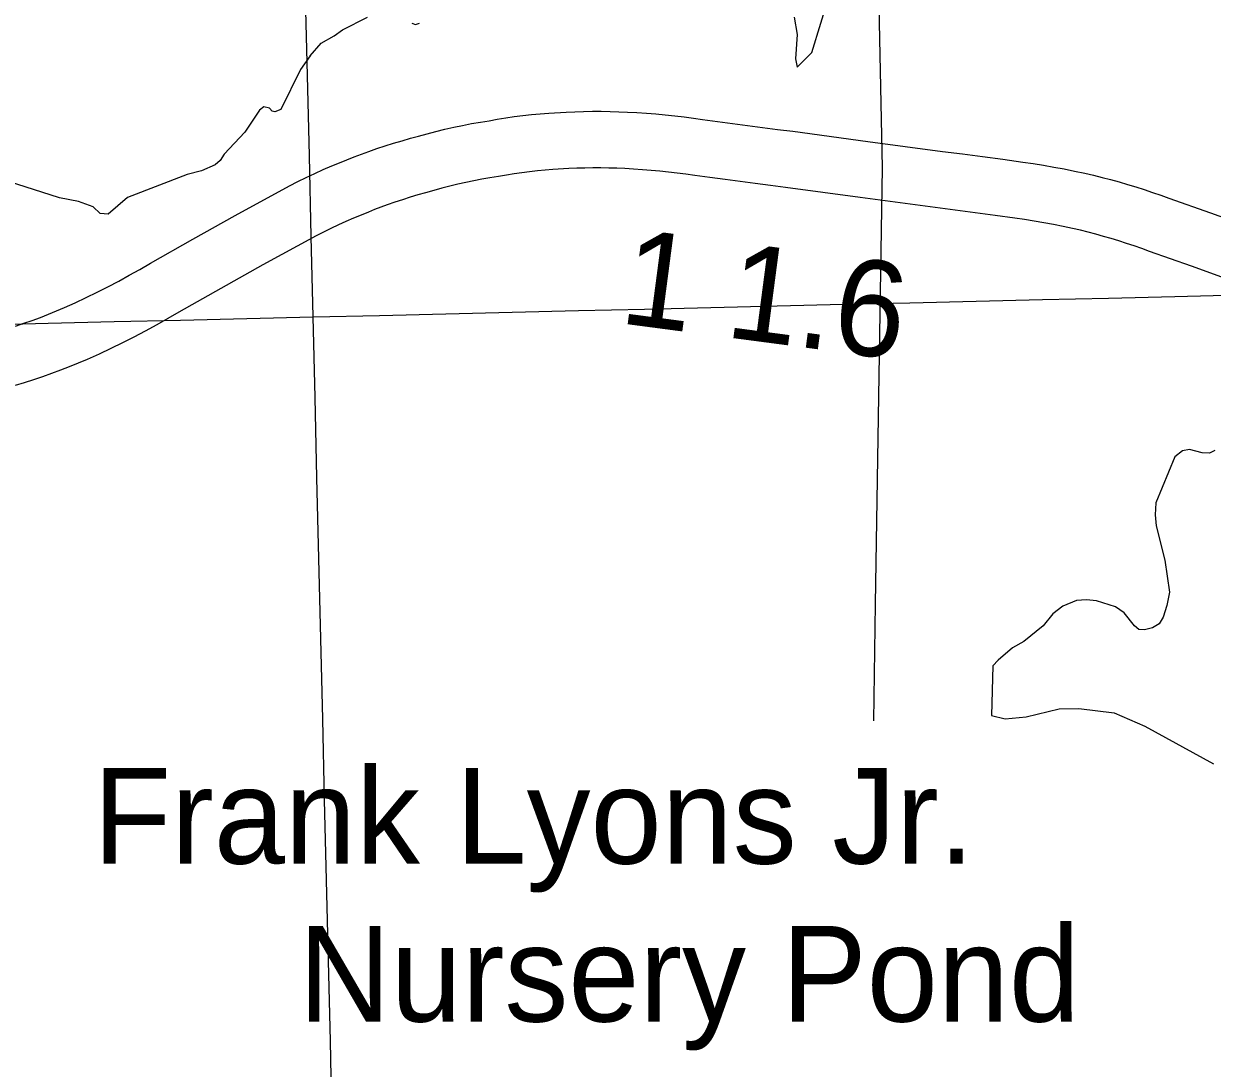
# Model space of a CAD drawing. Extents: x -19 to 366, y -4 to 359.
# Drawn here: x 134.672 to 135.666, y 199.103 to 199.977 of the extents above; entities that cross this region are included whole.
import ezdxf

# ---------------------------------------------------------------- set-up
doc = ezdxf.new("R2010")
doc.units = 0
for name, color, linetype in [('R_Axis Annot', 7, 'Continuous'), ('R_Border Prem', 7, 'Continuous'), ('R_Contour Annot', 7, 'Continuous'), ('R_Temp Easement', 7, 'Continuous'), ('Sheet Fence', 7, 'Continuous'), ('T_Vehicle Path Lt Minor', 7, 'Continuous')]:
    doc.layers.add(name, color=color, linetype=linetype)

msp = doc.modelspace()

# ---------------------------------------------------------------- linework, layer by layer
at = {"layer": 'R_Axis Annot'}
msp.add_lwpolyline([(135.38312, 199.3934), (135.3847, 199.49111), (135.39059, 199.85615), (135.38554, 200.09948)], dxfattribs=at)
at = {"layer": 'R_Border Prem'}
for points in [[(135.31655, 199.98229), (135.31921, 199.96788), (135.31771, 199.94739), (135.31923, 199.94056), (135.33132, 199.95271), (135.34639, 200.00202)], [(134.91173, 199.94991), (134.92079, 199.96054), (134.93175, 199.96661), (134.93855, 199.97154), (134.95971, 199.98217)], [(134.99676, 199.97725), (134.99978, 199.97611), (135.00318, 199.97725)], [(134.91173, 199.94991), (134.90357, 199.93839), (134.88704, 199.90515), (134.88215, 199.90319), (134.87987, 199.90353), (134.87756, 199.90616), (134.873, 199.90723), (134.86926, 199.90452), (134.85705, 199.88614), (134.83954, 199.86769), (134.83621, 199.86233), (134.8321, 199.85886), (134.82082, 199.85377), (134.80876, 199.85056), (134.75871, 199.83127), (134.74264, 199.81738), (134.73582, 199.81805), (134.73006, 199.82366), (134.71788, 199.82804), (134.70193, 199.83123), (134.63118, 199.85376)]]:
    msp.add_lwpolyline(points, dxfattribs=at)
at = {"layer": 'R_Contour Annot'}
for points in [[(134.96065, 199.86996), (134.96745, 199.87231), (134.97444, 199.87461), (134.98146, 199.87682), (134.98851, 199.87894), (134.99557, 199.88095), (135.00239, 199.8828), (135.00947, 199.88478), (135.01685, 199.88671), (135.02427, 199.88852), (135.03171, 199.89021), (135.03918, 199.89177), (135.04668, 199.89321), (135.0542, 199.89452), (135.0613, 199.89564), (135.06803, 199.89685), (135.07521, 199.89801), (135.08245, 199.89905), (135.08965, 199.89997), (135.0969, 199.90077), (135.10416, 199.90145), (135.11141, 199.90201), (135.1257, 199.90287), (135.13306, 199.9032), (135.14045, 199.90341), (135.14781, 199.90351), (135.15521, 199.90351), (135.16258, 199.90339), (135.16996, 199.90315), (135.17722, 199.90281), (135.18506, 199.9024), (135.19296, 199.90189), (135.20087, 199.90127), (135.20875, 199.90054), (135.21663, 199.89972), (135.22452, 199.89879), (135.23237, 199.89776), (135.23995, 199.89666), (135.25243, 199.89498), (135.265, 199.8933), (135.27756, 199.89164), (135.29015, 199.89), (135.30273, 199.88838), (135.31546, 199.88677), (135.37812, 199.87828), (135.4407, 199.87), (135.45745, 199.86784), (135.47428, 199.86563), (135.4911, 199.86337), (135.508, 199.86104), (135.51667, 199.85975), (135.52532, 199.85836), (135.53395, 199.85686), (135.54259, 199.85526), (135.55119, 199.85356), (135.55989, 199.85173), (135.56714, 199.85003), (135.57427, 199.84826), (135.58136, 199.8464), (135.58844, 199.84445), (135.59548, 199.8424), (135.60251, 199.84026), (135.60947, 199.83802), (135.61641, 199.8357), (135.62333, 199.83329), (135.62997, 199.83088), (135.66484, 199.8186), (135.69979, 199.80602)], [(134.66519, 199.72377), (134.67212, 199.72612), (134.67901, 199.72857), (134.68587, 199.73111), (134.69269, 199.73375), (134.69947, 199.7365), (134.70607, 199.73927), (134.71513, 199.74339), (134.72429, 199.74771), (134.73339, 199.75216), (134.74243, 199.75675), (134.75142, 199.76146), (134.76031, 199.76629), (134.76913, 199.77125), (134.77817, 199.7765), (134.81352, 199.79647), (134.84897, 199.81639), (134.89437, 199.84114), (134.90135, 199.84475), (134.90834, 199.84821), (134.91544, 199.85156), (134.92259, 199.85477), (134.92976, 199.85783), (134.93757, 199.861), (134.94229, 199.86301), (134.94839, 199.86545), (134.9545, 199.86777), (134.96065, 199.86996)], [(135.68364, 199.76151), (135.64896, 199.774), (135.61403, 199.78629), (135.60745, 199.78868), (135.60111, 199.7909), (135.59474, 199.79302), (135.58837, 199.79507), (135.58196, 199.79702), (135.57552, 199.79889), (135.56904, 199.80068), (135.56256, 199.80239), (135.55605, 199.804), (135.54961, 199.80551), (135.54172, 199.80717), (135.53369, 199.80876), (135.5256, 199.81025), (135.51752, 199.81166), (135.50942, 199.81296), (135.50129, 199.81417), (135.48471, 199.81645), (135.46804, 199.8187), (135.45134, 199.82089), (135.43457, 199.82305), (135.37183, 199.83135), (135.30931, 199.83982), (135.29674, 199.84142), (135.28407, 199.84304), (135.27141, 199.8447), (135.25877, 199.84636), (135.24613, 199.84805), (135.2334, 199.84977), (135.2259, 199.85085), (135.21867, 199.8518), (135.2114, 199.85266), (135.20412, 199.85342), (135.19685, 199.85409), (135.18956, 199.85466), (135.18228, 199.85514), (135.17488, 199.85552), (135.16811, 199.85584), (135.16145, 199.85605), (135.15479, 199.85616), (135.14812, 199.85617), (135.14147, 199.85607), (135.1348, 199.85588), (135.12816, 199.85558), (135.11465, 199.85477), (135.10819, 199.85427), (135.1017, 199.85367), (135.09526, 199.85296), (135.08883, 199.85213), (135.08238, 199.85121), (135.07599, 199.85017), (135.06915, 199.84895), (135.06197, 199.84781), (135.05521, 199.84663), (135.04848, 199.84535), (135.04179, 199.84394), (135.03511, 199.84243), (135.02847, 199.84081), (135.02184, 199.83908), (135.01497, 199.83716), (135.00826, 199.83533), (135.0018, 199.83349), (134.99537, 199.83156), (134.98897, 199.82955), (134.9826, 199.82745), (134.97612, 199.82521)], [(134.97612, 199.82521), (134.97084, 199.82332), (134.96557, 199.82133), (134.96035, 199.81924), (134.95575, 199.81728), (134.94798, 199.81413), (134.94158, 199.81139), (134.93523, 199.80854), (134.92897, 199.80559), (134.92275, 199.8025), (134.91658, 199.79931), (134.87189, 199.77496), (134.83676, 199.75522), (134.8017, 199.73541), (134.79262, 199.73014), (134.78322, 199.72486), (134.77371, 199.71969), (134.76414, 199.71467), (134.75451, 199.70978), (134.7448, 199.70503), (134.73504, 199.70043), (134.72504, 199.69588), (134.71751, 199.69272), (134.71011, 199.68973), (134.70265, 199.68684), (134.69518, 199.68406), (134.68763, 199.68139), (134.68007, 199.67882), (134.67247, 199.67636), (134.66484, 199.67401)]]:
    msp.add_lwpolyline(points, dxfattribs=at)
at = {"layer": 'R_Temp Easement'}
msp.add_lwpolyline([(135.66857, 199.61979), (135.66407, 199.61744), (135.65802, 199.61772), (135.64739, 199.62057), (135.64137, 199.61933), (135.63503, 199.61429), (135.61908, 199.57607), (135.6185, 199.56581), (135.61942, 199.55672), (135.62672, 199.52801), (135.63059, 199.50113), (135.62852, 199.49009), (135.62529, 199.48017), (135.62199, 199.4748), (135.61638, 199.47129), (135.60961, 199.46966), (135.60507, 199.46996), (135.60124, 199.47293), (135.59273, 199.48379), (135.58546, 199.48898), (135.5695, 199.49402), (135.56118, 199.49464), (135.55288, 199.49412), (135.54125, 199.48936), (135.53304, 199.48315), (135.5249, 199.47315), (135.50889, 199.45997), (135.49916, 199.45449), (135.48724, 199.44443), (135.4828, 199.43942), (135.48163, 199.39803), (135.49302, 199.39519), (135.51075, 199.39701), (135.53821, 199.40355), (135.55484, 199.40383), (135.58437, 199.40016), (135.60988, 199.38921), (135.66749, 199.35756)], dxfattribs=at)
at = {"layer": 'Sheet Fence'}
for points in [[(139.44064, 1.53154), (139.25106, 10.14733), (139.06082, 18.76327), (138.86992, 27.37935), (138.67836, 35.99557), (138.48613, 44.61194), (138.29325, 53.22845), (138.09971, 61.84511), (137.9055, 70.46191), (137.71065, 79.07885), (137.51513, 87.69595), (137.31896, 96.31318), (137.12214, 104.93057), (136.92466, 113.54809), (136.72653, 122.16577), (136.52775, 130.78359), (136.32832, 139.40156), (136.12824, 148.01968), (135.9275, 156.63794), (135.72612, 165.25636), (135.5241, 173.87492), (135.32143, 182.49362), (135.11811, 191.11248), (134.91415, 199.73149), (134.70954, 208.35064), (134.50429, 216.96995), (134.2984, 225.5894), (134.09187, 234.209), (133.8847, 242.82876), (133.6769, 251.44866), (133.46845, 260.06872), (133.25937, 268.68892), (133.04965, 277.30928), (132.8393, 285.92978), (132.62831, 294.55044), (132.41669, 303.17125), (132.20444, 311.79221), (131.99156, 320.41333), (131.77805, 329.0346), (131.56391, 337.65601), (131.34914, 346.27759)], [(0, 198.13258), (7.10141, 198.13701), (14.2028, 198.15029), (21.30418, 198.17244), (28.40552, 198.20345), (35.50682, 198.24331), (42.60806, 198.29203), (49.70923, 198.34961), (56.81033, 198.41605), (63.91134, 198.49135), (71.01225, 198.5755), (78.11305, 198.66852), (85.21373, 198.77039), (92.31428, 198.88112), (99.41468, 199.0007), (106.51492, 199.12915), (113.61501, 199.26645), (120.71491, 199.4126), (127.81463, 199.56762), (134.91415, 199.73149), (142.01345, 199.90421), (149.11254, 200.0858), (156.2114, 200.27623), (163.31001, 200.47553), (170.40837, 200.68367), (177.50646, 200.90068), (184.60427, 201.12653), (191.7018, 201.36125), (198.79903, 201.60481), (205.89596, 201.85723), (212.99256, 202.1185), (220.08883, 202.38862), (227.18475, 202.6676), (234.28033, 202.95542), (241.37554, 203.2521), (248.47037, 203.55763), (255.56482, 203.87201), (262.65887, 204.19524), (269.75251, 204.52732), (276.84573, 204.86824), (283.93852, 205.21802), (291.03086, 205.57664), (298.12276, 205.94411), (305.21419, 206.32042), (312.30515, 206.70559), (319.39562, 207.09959), (326.48559, 207.50244), (333.57505, 207.91414), (340.664, 208.33468)], [(0, 189.51617), (7.11214, 189.52059), (14.22427, 189.53386), (21.33637, 189.55597), (28.44845, 189.58693), (35.56048, 189.62672), (42.67245, 189.67537), (49.78436, 189.73285), (56.89619, 189.79918), (64.00793, 189.87436), (71.11958, 189.95838), (78.23111, 190.05124), (85.34253, 190.15294), (92.45381, 190.26349), (99.56495, 190.38288), (106.67593, 190.51112), (113.78675, 190.6482), (120.89739, 190.79412), (128.00785, 190.94888), (135.11811, 191.11248), (142.22816, 191.28493), (149.33799, 191.46621), (156.44759, 191.65634), (163.55694, 191.85531), (170.66605, 192.06312), (177.77489, 192.27977), (184.88345, 192.50526), (191.99173, 192.73959), (199.09971, 192.98276), (206.20739, 193.23477), (213.31474, 193.49561), (220.42177, 193.7653), (227.52845, 194.04382), (234.63479, 194.33118), (241.74076, 194.62738), (248.84635, 194.93241), (255.95157, 195.24628), (263.05638, 195.56898), (270.16079, 195.90052), (277.26478, 196.24089), (284.36834, 196.5901), (291.47147, 196.94814), (298.57414, 197.31501), (305.67635, 197.69072), (312.77809, 198.07525), (319.87934, 198.46862), (326.9801, 198.87082), (334.08035, 199.28185), (341.18009, 199.7017)]]:
    msp.add_spline(points, degree=3, dxfattribs=at)

# ---------------------------------------------------------------- texts
at = {"layer": 'R_Temp Easement'}
for s, p in [('Frank Lyons Jr.', (134.73006, 199.27404)), ('Nursery Pond', (134.90178, 199.14192))]:
    msp.add_text(s, height=0.08, dxfattribs=at).set_placement(p)
at = {"layer": 'T_Vehicle Path Lt Minor'}
msp.add_text('1 1.6', height=0.08, rotation=352.50419, dxfattribs=at).set_placement((135.16919, 199.72641))

doc.saveas('drawing.dxf')
